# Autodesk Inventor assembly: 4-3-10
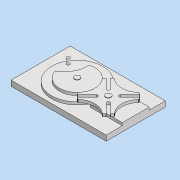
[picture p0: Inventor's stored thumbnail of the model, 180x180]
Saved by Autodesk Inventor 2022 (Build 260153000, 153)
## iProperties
Created: 2021-07
Part Number: 4-3-10
Document SubType Name: Assembly
Designer: DesignLab
Author: DesignLab
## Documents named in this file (5)
- d:\Users\DesignLab\Desktop\ver2022\ch04\4-3-10.iam
- d:\Users\DesignLab\Desktop\ver2022\ch04\03-ベース板_完成.ipt
- d:\Users\DesignLab\Desktop\ver2022\ch04\01-駆動車_完成.ipt
- d:\Users\DesignLab\Desktop\ver2022\ch04\02-従動車_完成.ipt
- d:\Users\DesignLab\Desktop\ver2022\ch04\04-ピン_完成.ipt
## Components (5 placed, 4 different names)
1. 03-ベース板_完成:1 — 回転:1, 回転:2
2. 01-駆動車_完成:1 — 回転:1, フラッシュ:1
3. 02-従動車_完成:1 — 回転:2, 回転:3
4. 04-ピン_完成:1 — フラッシュ:1
5. 04-ピン_完成:2 — 回転:3
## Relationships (4: RevoluteJoint 3, Flush 1)
- 回転:1 [RevoluteJoint]: 03-ベース板_完成:1 ↔ 01-駆動車_完成:1
- 回転:2 [RevoluteJoint]: 03-ベース板_完成:1 ↔ 02-従動車_完成:1
- フラッシュ:1 [Flush]: 01-駆動車_完成:1 ↔ 04-ピン_完成:1
- 回転:3 [RevoluteJoint]: 02-従動車_完成:1 ↔ 04-ピン_完成:2
